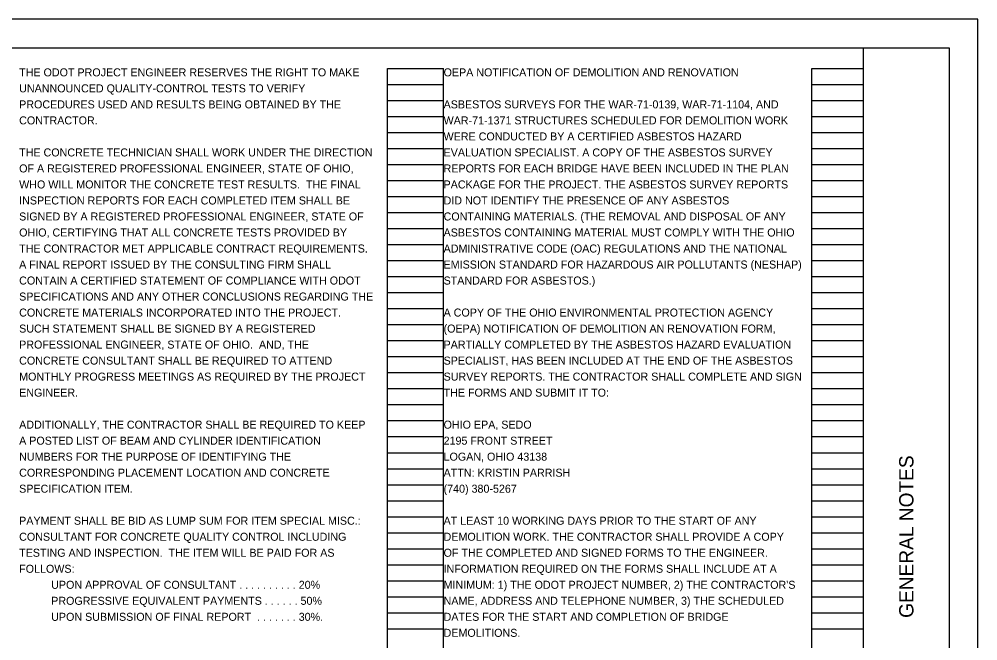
# Model space of a CAD drawing. Extents: x 0 to 34, y 0 to 22.
# Drawn here: x 17.24 to 34, y 11.13 to 22 of the extents above; entities that cross this region are included whole.
import ezdxf

# ---------------------------------------------------------------- set-up
doc = ezdxf.new("R2010")
doc.units = 0
for name, color, linetype in [('SH_Border', 7, 'Continuous'), ('SH_Cut_Line', 7, 'Continuous'), ('SH_Data', 7, 'Continuous'), ('SH_Text', 7, 'Continuous')]:
    doc.layers.add(name, color=color, linetype=linetype)

msp = doc.modelspace()

# ---------------------------------------------------------------- linework, layer by layer
at = {"layer": 'SH_Border'}
msp.add_line((32, 0.5), (32, 21.5), dxfattribs=at)
msp.add_lwpolyline([(1.5, 21.5), (33.5, 21.5), (33.5, 0.5), (1.5, 0.5)], close=True, dxfattribs=at)
at = {"layer": 'SH_Cut_Line'}
msp.add_lwpolyline([(0, 0), (34, 0), (34, 22), (0, 22)], close=True, dxfattribs=at)
at = {"layer": 'SH_Data'}
for p, q in [((23.68, 0.98), (23.68, 21.14)), ((23.68, 21.14), (24.66, 21.14)), ((24.66, 0.98), (24.66, 21.14)), ((31.1, 0.98), (31.1, 21.14)), ((31.1, 21.14), (32, 21.14)), ((32, 0.98), (32, 21.14)), ((23.68, 20.86), (24.66, 20.86)), ((31.1, 20.86), (32, 20.86)), ((23.68, 20.58), (24.66, 20.58)), ((31.1, 20.58), (32, 20.58)), ((23.68, 20.3), (24.66, 20.3)), ((31.1, 20.3), (32, 20.3)), ((23.68, 20.02), (24.66, 20.02)), ((31.1, 20.02), (32, 20.02)), ((23.68, 19.74), (24.66, 19.74)), ((31.1, 19.74), (32, 19.74)), ((23.68, 19.46), (24.66, 19.46)), ((31.1, 19.46), (32, 19.46)), ((23.68, 19.18), (24.66, 19.18)), ((31.1, 19.18), (32, 19.18)), ((23.68, 18.9), (24.66, 18.9)), ((31.1, 18.9), (32, 18.9)), ((23.68, 18.62), (24.66, 18.62)), ((31.1, 18.62), (32, 18.62)), ((23.68, 18.34), (24.66, 18.34)), ((31.1, 18.34), (32, 18.34)), ((23.68, 18.06), (24.66, 18.06)), ((31.1, 18.06), (32, 18.06)), ((23.68, 17.78), (24.66, 17.78)), ((31.1, 17.78), (32, 17.78)), ((23.68, 17.5), (24.66, 17.5)), ((31.1, 17.5), (32, 17.5)), ((23.68, 17.22), (24.66, 17.22)), ((31.1, 17.22), (32, 17.22)), ((23.68, 16.94), (24.66, 16.94)), ((31.1, 16.94), (32, 16.94)), ((23.68, 16.66), (24.66, 16.66)), ((31.1, 16.66), (32, 16.66)), ((23.68, 16.38), (24.66, 16.38)), ((31.1, 16.38), (32, 16.38)), ((23.68, 16.1), (24.66, 16.1)), ((31.1, 16.1), (32, 16.1)), ((23.68, 15.82), (24.66, 15.82)), ((31.1, 15.82), (32, 15.82)), ((23.68, 15.54), (24.66, 15.54)), ((31.1, 15.54), (32, 15.54)), ((23.68, 15.26), (24.66, 15.26)), ((31.1, 15.26), (32, 15.26)), ((23.68, 14.98), (24.66, 14.98)), ((31.1, 14.98), (32, 14.98)), ((23.68, 14.7), (24.66, 14.7)), ((31.1, 14.7), (32, 14.7)), ((23.68, 14.42), (24.66, 14.42)), ((31.1, 14.42), (32, 14.42)), ((23.68, 14.14), (24.66, 14.14)), ((31.1, 14.14), (32, 14.14)), ((23.68, 13.86), (24.66, 13.86)), ((31.1, 13.86), (32, 13.86)), ((23.68, 13.58), (24.66, 13.58)), ((31.1, 13.58), (32, 13.58)), ((23.68, 13.3), (24.66, 13.3)), ((31.1, 13.3), (32, 13.3)), ((23.68, 13.02), (24.66, 13.02)), ((31.1, 13.02), (32, 13.02)), ((23.68, 12.74), (24.66, 12.74)), ((31.1, 12.74), (32, 12.74)), ((23.68, 12.46), (24.66, 12.46)), ((31.1, 12.46), (32, 12.46)), ((23.68, 12.18), (24.66, 12.18)), ((31.1, 12.18), (32, 12.18)), ((23.68, 11.9), (24.66, 11.9)), ((31.1, 11.9), (32, 11.9)), ((23.68, 11.62), (24.66, 11.62)), ((31.1, 11.62), (32, 11.62)), ((23.68, 11.34), (24.66, 11.34)), ((31.1, 11.34), (32, 11.34))]:
    msp.add_line(p, q, dxfattribs=at)

# ---------------------------------------------------------------- texts
msp.add_text('GENERAL NOTES', height=0.25, rotation=90, dxfattribs=at).set_placement((32.875, 11.531))
at = {"layer": 'SH_Text'}
for s, p in [('THE ODOT PROJECT ENGINEER RESERVES THE RIGHT TO MAKE ', (17.24, 21)), ('OEPA NOTIFICATION OF DEMOLITION AND RENOVATION', (24.66, 21)), ('UNANNOUNCED QUALITY-CONTROL TESTS TO VERIFY ', (17.24, 20.72)), ('PROCEDURES USED AND RESULTS BEING OBTAINED BY THE ', (17.24, 20.44)), ('ASBESTOS SURVEYS FOR THE WAR-71-0139, WAR-71-1104, AND ', (24.66, 20.44)), ('CONTRACTOR.', (17.24, 20.16)), ('WAR-71-1371 STRUCTURES SCHEDULED FOR DEMOLITION WORK ', (24.66, 20.16)), ('WERE CONDUCTED BY A CERTIFIED ASBESTOS HAZARD ', (24.66, 19.88)), ('THE CONCRETE TECHNICIAN SHALL WORK UNDER THE DIRECTION ', (17.24, 19.6)), ('EVALUATION SPECIALIST. A COPY OF THE ASBESTOS SURVEY ', (24.66, 19.6)), ('OF A REGISTERED PROFESSIONAL ENGINEER, STATE OF OHIO, ', (17.24, 19.32)), ('REPORTS FOR EACH BRIDGE HAVE BEEN INCLUDED IN THE PLAN ', (24.66, 19.32)), ('WHO WILL MONITOR THE CONCRETE TEST RESULTS.  THE FINAL ', (17.24, 19.04)), ('PACKAGE FOR THE PROJECT. THE ASBESTOS SURVEY REPORTS ', (24.66, 19.04)), ('INSPECTION REPORTS FOR EACH COMPLETED ITEM SHALL BE ', (17.24, 18.76)), ('DID NOT IDENTIFY THE PRESENCE OF ANY ASBESTOS ', (24.66, 18.76)), ('SIGNED BY A REGISTERED PROFESSIONAL ENGINEER, STATE OF ', (17.24, 18.48)), ('CONTAINING MATERIALS. (THE REMOVAL AND DISPOSAL OF ANY ', (24.66, 18.48)), ('OHIO, CERTIFYING THAT ALL CONCRETE TESTS PROVIDED BY ', (17.24, 18.2)), ('ASBESTOS CONTAINING MATERIAL MUST COMPLY WITH THE OHIO ', (24.66, 18.2)), ('THE CONTRACTOR MET APPLICABLE CONTRACT REQUIREMENTS.  ', (17.24, 17.92)), ('ADMINISTRATIVE CODE (OAC) REGULATIONS AND THE NATIONAL ', (24.66, 17.92)), ('A FINAL REPORT ISSUED BY THE CONSULTING FIRM SHALL ', (17.24, 17.64)), ('EMISSION STANDARD FOR HAZARDOUS AIR POLLUTANTS (NESHAP) ', (24.66, 17.64)), ('CONTAIN A CERTIFIED STATEMENT OF COMPLIANCE WITH ODOT ', (17.24, 17.36)), ('STANDARD FOR ASBESTOS.)', (24.66, 17.36)), ('SPECIFICATIONS AND ANY OTHER CONCLUSIONS REGARDING THE ', (17.24, 17.08)), ('CONCRETE MATERIALS INCORPORATED INTO THE PROJECT.  ', (17.24, 16.8)), ('A COPY OF THE OHIO ENVIRONMENTAL PROTECTION AGENCY ', (24.66, 16.8)), ('SUCH STATEMENT SHALL BE SIGNED BY A REGISTERED ', (17.24, 16.52)), ('(OEPA) NOTIFICATION OF DEMOLITION AN RENOVATION FORM, ', (24.66, 16.52)), ('PROFESSIONAL ENGINEER, STATE OF OHIO.  AND, THE ', (17.24, 16.24)), ('PARTIALLY COMPLETED BY THE ASBESTOS HAZARD EVALUATION ', (24.66, 16.24)), ('CONCRETE CONSULTANT SHALL BE REQUIRED TO ATTEND ', (17.24, 15.96)), ('SPECIALIST, HAS BEEN INCLUDED AT THE END OF THE ASBESTOS ', (24.66, 15.96)), ('MONTHLY PROGRESS MEETINGS AS REQUIRED BY THE PROJECT ', (17.24, 15.68)), ('SURVEY REPORTS. THE CONTRACTOR SHALL COMPLETE AND SIGN ', (24.66, 15.68)), ('ENGINEER.', (17.24, 15.4)), ('THE FORMS AND SUBMIT IT TO:', (24.66, 15.4)), ('ADDITIONALLY, THE CONTRACTOR SHALL BE REQUIRED TO KEEP ', (17.24, 14.84)), ('OHIO EPA, SEDO', (24.66, 14.84)), ('A POSTED LIST OF BEAM AND CYLINDER IDENTIFICATION ', (17.24, 14.56)), ('2195 FRONT STREET', (24.66, 14.56)), ('NUMBERS FOR THE PURPOSE OF IDENTIFYING THE ', (17.24, 14.28)), ('LOGAN, OHIO 43138', (24.66, 14.28)), ('CORRESPONDING PLACEMENT LOCATION AND CONCRETE ', (17.24, 14)), ('ATTN: KRISTIN PARRISH', (24.66, 14)), ('SPECIFICATION ITEM.', (17.24, 13.72)), ('(740) 380-5267', (24.66, 13.72)), ('PAYMENT SHALL BE BID AS LUMP SUM FOR ITEM SPECIAL MISC.:  ', (17.24, 13.16)), ('AT LEAST 10 WORKING DAYS PRIOR TO THE START OF ANY ', (24.66, 13.16)), ('CONSULTANT FOR CONCRETE QUALITY CONTROL INCLUDING ', (17.24, 12.88)), ('DEMOLITION WORK. THE CONTRACTOR SHALL PROVIDE A COPY ', (24.66, 12.88)), ('TESTING AND INSPECTION.  THE ITEM WILL BE PAID FOR AS ', (17.24, 12.6)), ('OF THE COMPLETED AND SIGNED FORMS TO THE ENGINEER. ', (24.66, 12.6)), ('FOLLOWS:', (17.24, 12.32)), ('INFORMATION REQUIRED ON THE FORMS SHALL INCLUDE AT A ', (24.66, 12.32)), ('UPON APPROVAL OF CONSULTANT . . . . . . . . . . 20%', (17.8, 12.04)), ("MINIMUM: 1) THE ODOT PROJECT NUMBER, 2) THE CONTRACTOR'S ", (24.66, 12.04)), ('PROGRESSIVE EQUIVALENT PAYMENTS . . . . . . 50%', (17.8, 11.76)), ('NAME, ADDRESS AND TELEPHONE NUMBER, 3) THE SCHEDULED ', (24.66, 11.76)), ('UPON SUBMISSION OF FINAL REPORT  . . . . . . . 30%.', (17.8, 11.48)), ('DATES FOR THE START AND COMPLETION OF BRIDGE ', (24.66, 11.48)), ('DEMOLITIONS.', (24.66, 11.2))]:
    msp.add_text(s, height=0.14, dxfattribs=at).set_placement(p)

doc.saveas('drawing.dxf')
